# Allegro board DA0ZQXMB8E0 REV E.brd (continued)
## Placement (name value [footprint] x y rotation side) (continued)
PR202  *100k/f_4  [RC0402]  81.04 66.52 270 bottom
PR203  -  [RC0402]  84.75 66.3 270 bottom
PR204  *22.6k/f_4  [RC0402]  74.16 65.76 270 bottom
PR205  *100k/f_4  [RC0402]  82.8 62.56 180 bottom
PR206  -  [RC0402]  81.2 60.5 0 bottom
PR207  *2.2/f_6  [RC0603]  86.73 59.49 270 bottom
PR208  0.01/f_0612  [RC3216]  102.73 50.95 270 bottom
PR209  *short 0_4  [SHORT0402]  83.91 49.96 0 bottom
PR210  7.5_6  [RC0603]  81.2 49.79 0 bottom
PR211  *short 0_4  [SHORT0402]  83.91 48.8 0 bottom
PR212  10_6  [RC0603]  81.2 48.59 0 bottom
PR213  10k_4  [RC0402]  78.58 48.46 270 bottom
PR214  *100k_4  [RC0402]  76.55 47.7 180 bottom
PR215  -  [RC0402]  76.55 46.69 180 bottom
PR216  1/f_6  [RC0603]  57.9 46.46 180 bottom
PR217  *short 0_4  [SHORT0402]  50.69 46.15 180 bottom
PR218  -  [RC0402]  76.55 45.65 0 bottom
PR219  *short 0_4  [SHORT0402]  50.69 45.11 180 bottom
PR220  -  [RC0402]  72.89 45.11 270 bottom
PR221  *short 0_4  [SHORT0402]  73.91 45.11 270 bottom
PR222  *short 0_4  [SHORT0402]  76.55 44.63 0 bottom
PR223  -  [RC0402]  69.31 44.38 180 bottom
PR224  *short 0_6  [SHORT0603]  85.08 44.35 0 bottom
PR225  *short 0_4  [SHORT0402#2]  57.95 43.99 0 bottom
PR226  *short 0_4  [SHORT0402#2]  76.55 43.61 0 bottom
PR227  *0_4  [RC0402]  73.4 43.59 0 bottom
PR228  -  [RC0402]  57.95 42.95 0 bottom
PR229  -  [RC0402]  70.6 41.68 90 bottom
PR230  -  [RC0402]  78.48 40.54 270 bottom
PR231  *0_4  [RC0402]  79.49 40.54 90 bottom
PR232  10k_4  [RC0402]  80.51 40.54 90 bottom
PR233  -  [RC0402]  74.16 39.78 0 bottom
PR234  -  [RC0402]  106.16 39.65 180 bottom
PR235  10k_4  [RC0402]  108.45 39.65 180 bottom
PR236  22_8  [RC0805#2]  229.48 69.5 180 top
PR237  1m_6  [RC0603#2]  223.13 62 0 top
PR238  1m_6  [RC0603#2]  223.13 63.27 180 top
PR239  1m_6  [RC0603#2]  223.13 65.81 180 top
PR240  -  [RC0603#2]  223.13 64.54 180 top
PR241  -  [RC0402#2]  106.62 156.84 0 bottom
PR242  *short 0_4  [SHORT0402]  80.28 38.53 180 bottom
PU6  -  [QFN20-3X3-4-26P]  226.38 76.28 90 top
PU7  -  [QFN32-4X4-4-42P-1H]  78.5 64.19 180 top
PU8  tps54318rter  [QFN16-3X3-5-22P]  65.78 44.6 0 top
PU9  ev@nb671  [QFN14-3X3-4-16P#2]  100.8 156.19 270 bottom
PU10  nb670gq-z  [QFN14-3X3-4-16P]  211.14 151.87 0 bottom
PU11  -  [QFN20-3X3-4-21P-0_8H]  198.24 149.1 0 bottom
PU12  tps51211dscr  [SON10-3X3-5-16P]  196.51 137.62 0 bottom
PU13  as393mtr-e1  [SOIC8-6-1_27]  176.52 124.54 270 bottom
PU14  csd97374cq4m  [SON8-4_5X3_5-5-9P-SMT]  87.88 72.93 0 bottom
PU15  *csd97374cq4m  [SON8-4_5X3_5-5-9P-SMT]  88 63.7 0 bottom
PU16  nb671  [QFN14-3X3-4-16P]  54.12 45.95 90 bottom
PU17  bq24737rgrr  [PVQFN20-3_5X3_5-5-25P]  80.51 44.6 180 bottom
PU18  -  [SOT23-6-2_8-95-6P]  144.64 43.33 90 bottom
Q6  -  [SC70-2_1-65-6P]  91.05 144.43 90 top
Q7  ev@2n7002k  [SOT23_213-3_3-2#2]  155.95 144.05 90 top
Q8  -  [UMT_213-3-1_3]  96.13 141.63 0 top
Q9  ev@2n7002k  [SOT23_213-3_3-2]  160.01 141.63 90 top
Q10  -  [SC70-2_1-65-6P]  95.37 138.84 180 top
Q11  -  [SOT23_213-3_3-2#2]  155.95 137.44 0 top
Q12  ev@2n7002k  [SOT23_213-3_3-2]  154.04 130.46 90 top
Q13  -  [SOT23_213-3_3-2]  230.88 121.44 0 top
Q14  -  [SC70-2_1-65-6P]  145.15 119.66 180 top
Q15  -  [SOT23_213-3_3-2]  144.9 114.96 90 top
Q16  -  [SOT23_213-3_3-2]  111.24 114.58 270 top
Q17  -  [SC70-2_1-65-6P]  129.81 113.92 180 top
Q18  -  [SOT23_213-3_3-2]  215.92 111.63 90 top
Q19  -  [SOT23_213-3_3-2]  125.72 111.41 180 top
Q20  -  [SOT23_213-3_3-2]  147.95 104.8 90 top
Q21  -  [UMT_213-3-1_3]  26.53 47.65 270 top
Q22  -  [SOT23_213-3_3-2]  217.16 42.7 180 top
Q23  -  [SOT23_213-3_3-2]  17.39 42.57 0 top
Q24  -  [SOT23_213-3_3-2]  21.58 42.57 0 top
Q25  -  [SOT23_213-3_3-2]  33.39 42.57 0 top
Q26  -  [SC70-2_1-65-6P]  225.29 39.91 90 top
Q27  -  [SOT23_213-3_3-2]  17.39 38.76 180 top
Q28  -  [SOT23_213-3_3-2]  21.58 38.76 0 top
Q29  -  [SOT23_213-3_3-2#2]  140.58 160.68 0 bottom
Q30  -  [SC70-2_1-65-6P#2]  145.34 160.65 0 bottom
Q31  -  [UMT_213-3-1_3#2]  155.95 156.24 270 bottom
Q32  -  [SOT23_213-3_3-2#2]  160.52 155.73 270 bottom
Q33  -  [SOT23_213-3_3-2]  155.95 150.01 90 bottom
Q34  -  [SOT23_213-3_3-2#2]  159.38 139.09 0 bottom
Q35  -  [SOT23_213-3_3-2]  95.5 138.08 90 bottom
Q36  -  [SOT23_213-3_3-2#2]  156.07 135.03 90 bottom
Q37  -  [UMT_213-3-1_3#2]  156.84 129.82 90 bottom
Q38  -  [SOT23_213-3_3-2]  106.42 60.48 0 bottom
Q39  -  [UMT_213-3-1_3#2]  207.38 57.94 180 bottom
Q40  -  [UMT_213-3-1_3]  98.29 57.3 0 bottom
Q41  -  [SOT23_213-3_3-2]  150.74 55.65 90 bottom
Q42  -  [SOT23_213-3_3-2]  148.2 39.65 90 bottom
Q43  fdv301n  [SOT23_213-3_3-2]  153.28 39.65 270 bottom
Q44  -  [SC70-2_1-65-6P]  48.38 39.14 0 bottom
Q45  -  [SOT23_213-3_3-2]  20.57 36.6 270 bottom
Q53  -  [SOT23_213-3_3-2#2]  45.36 44.76 90 bottom
Q54  -  [SOT23_213-3_3-2#2]  219.96 131.5 90 top
R6  -  [SHORT0603]  80.26 153.32 0 top
R7  *100k_4  [RC0402]  92.96 153.06 0 top
R8  -  [RC0402#2]  105.02 153.06 0 top
R9  *0_4  [RC0402]  220.34 152.81 270 top
R10  *0_4  [RC0402]  221.35 152.81 270 top
R11  *0_4  [RC0402]  222.37 152.81 270 top
R12  -  [SHORT0603]  91.05 152.3 90 top
R13  -  [RC0402#2]  105.02 152.05 180 top
R14  *10k/f_4  [RC0402#2]  147.69 152.05 270 top
R15  ev@10k/f_4  [RC0402#2]  148.71 152.05 270 top
R16  *10k/f_4  [RC0402#2]  149.72 152.05 270 top
R17  sp@10k/f_4  [RC0402#2]  150.74 152.05 270 top
R18  *10k/f_4  [RC0402#2]  151.76 152.05 270 top
R19  *4.99k/f_4  [RC0402#2]  152.77 152.05 270 top
R20  -  [RC0402#2]  153.79 152.05 270 top
R21  sp@10k/f_4  [RC0402#2]  154.8 152.05 270 top
R22  -  [SHORT0603]  82.29 151.79 90 top
R23  -  [RC0402#2]  142.23 151.16 270 top
R24  -  [RC0402#2]  144.59 151.41 270 top
R25  -  [RC0402#2]  145.66 151.28 270 top
R26  -  [RC0402#2]  146.68 151.16 270 top
R27  -  [SHORT0603]  74.54 150.4 90 top
R28  -  [SHORT0603]  75.94 150.4 90 top
R29  ev@51.1/f_4  [RC0402#2]  131.69 150.27 90 top
R30  *short_8  [SHORT0805]  220.84 150.14 0 top
R31  -  [RC0402#2]  105.02 150.01 180 top
R32  -  [RC0402#2]  132.71 149.89 90 top
R33  sp@10k/f_4  [RC0402#2]  150.11 149.91 90 top
R34  -  [RC0402#2]  151.12 149.91 90 top
R35  -  [RC0402#2]  152.26 149.91 90 top
R36  sp@10k/f_4  [RC0402#2]  153.28 149.91 90 top
R37  sp@10k/f_4  [RC0402#2]  154.3 149.91 90 top
R38  -  [RC0402]  84.07 149.51 180 top
R39  -  [RC0402]  89.78 148.74 180 top
R40  -  [RC0402]  92.07 148.74 0 top
R41  ev@10k/f_4  [RC0402#2]  105.02 148.49 180 top
R42  *100k_4  [RC0402]  84.07 148.24 180 top
R43  ev@10k/f_4  [RC0402#2]  152.65 147.73 180 top
R44  -  [RC0402#2]  132.96 147.6 180 top
R45  ev@10k/f_4  [RC0402#2]  105.02 147.47 180 top
R46  *0_4  [RC0402]  89.78 147.22 0 top
R47  *0_4  [RC0402]  92.07 147.22 0 top
R48  10k_4  [RC0402]  95.24 147.22 90 top
R49  *100k_4  [RC0402]  93.84 146.97 90 top
R50  *0_4  [RC0402#2]  152.65 146.71 0 top
R51  ev@10k/f_4  [RC0402#2]  152.65 145.7 180 top
R52  -  [RC0402#2]  149.98 145.32 270 top
R53  *60.4_4  [RC0402#2]  120.13 144.81 90 top
R54  ev@10k/f_4  [RC0402#2]  159 144.81 270 top
R55  -  [RC0402#2]  118.87 144.81 90 top
R56  ev@10k/f_4  [RC0402]  105.02 144.43 0 top
R57  -  [RC0402#2]  160.77 144.3 180 top
R58  *60.4_4  [RC0402#2]  135.53 143.92 0 top
R59  *0_8  [RC0805]  221.99 143.03 0 top
R60  -  [SHORT0402#2]  222.75 141.12 0 top
R61  ev@10k/f_4  [RC0402]  156.2 141 0 top
R62  *10k/f_4  [RC0402#2]  154.68 140.49 270 top
R63  -  [SHORT0402#2]  222.75 140.11 0 top
R64  *0_4  [RC0402]  156.2 139.98 0 top
R65  10k_4  [RC0402]  92.7 139.6 270 top
R66  -  [SHORT0402]  222.75 139.09 0 top
R67  -  [RC0402]  98.29 138.84 270 top
R68  -  [SHORT0402#2]  99.56 138.84 270 top
R69  0_4  [RC0402]  100.58 138.84 270 top
R70  -  [SHORT0402]  220.72 138.46 270 top
R71  -  [SHORT0402]  222.75 138.08 0 top
R72  -  [SHORT0402]  222.75 137.06 0 top
R73  -  [RC0402#2]  105.02 135.54 180 top
R74  *0_4  [RC0402#2]  154.55 134.39 90 top
R75  *0_4  [RC0402#2]  155.82 134.39 90 top
R76  -  [RC0402#2]  105.02 133.5 0 top
R77  -  [SHORT0402]  95.14 132.92 270 top
R78  -  [RC0402]  96.41 132.92 270 top
R79  -  [RC0402#2]  105.02 132.23 180 top
R80  -  [RC0402#2]  138.29 131.98 270 top
R81  ev@10k/f_4  [RC0402#2]  150.99 131.98 180 top
R82  ev@10k/f_4  [RC0402]  105.02 131.09 0 top
R83  *0_4  [RC0402]  150.99 130.96 180 top
R84  -  [RC0402#2]  105.53 129.44 90 top
R85  ev@10k/f_4  [RC0402#2]  148.96 129.82 270 top
R86  ev@2.49k/f_4  [RC0402#2]  131.82 128.68 270 top
R87  10k_4  [RC0402]  198.75 126.27 0 top
R88  tpm@2.2_6  [RC0603]  225.8 124.23 180 top
R89  -  [RC0402]  231.77 123.98 0 top
R90  -  [RC0402]  228.21 122.46 270 top
R91  -  [RC0402]  143.76 121.44 180 top
R92  0_4  [RC0402]  146.04 121.44 0 top
R93  -  [RC0402]  225.42 120.68 180 top
R94  -  [RC0402]  153.61 120.12 180 top
R95  *20k_4  [RC0402]  227.7 119.92 0 top
R96  -  [RC0402]  227.7 120.93 180 top
R97  -  [RC0402]  143.76 117.88 180 top
R98  0_4  [RC0402]  146.04 117.88 0 top
R99  -  [RC0402]  211.5 117.3 180 top
R100  tpm@0_4  [RC0402]  214.06 116.44 180 top
R101  *short_8  [SHORT0805]  105.53 116.36 90 top
R102  10k_4  [RC0402]  107.31 115.85 270 top
R103  10k_4  [RC0402]  108.7 115.85 270 top
R104  4.7k_4  [RC0402]  130.93 115.6 180 top
R105  -  [RC0402]  217.24 114.48 180 top
R106  -  [RC0402]  221.61 114.2 180 top
R107  -  [RC0402]  190.01 114.1 90 top
R108  -  [RC0402]  191.05 114.1 90 top
R109  -  [RC0402]  193.16 114.1 90 top
R110  -  [RC0402]  194.17 114.1 90 top
R111  -  [RC0402]  195.22 114.1 90 top
R112  -  [RC0402]  196.28 114.1 90 top
R113  -  [RC0402]  197.32 114.1 90 top
R114  -  [RC0402]  198.37 114.1 90 top
R115  -  [RC0402]  199.51 114.1 90 top
R116  -  [RC0402]  192.14 114.07 90 top
R117  4.7k_4  [RC0402]  127.12 114.45 90 top
R118  -  [RC0402]  201.79 113.77 0 top
R119  1k_4  [RC0402]  108.7 113.57 90 top
R120  -  [RC0402]  188.33 113.57 180 top
R121  -  [RC0402]  165.98 113.06 180 top
R122  -  [RC0402]  201.79 112.73 0 top
R123  -  [RC0402]  131.06 112.17 0 top
R124  -  [RC0402]  128.92 112.14 180 top
R125  -  [SHORT0402#2]  121.94 112.42 180 top
R126  *0_4  [RC0402]  172.33 111.79 180 top
R127  -  [RC0402]  201.79 111.69 0 top
R128  -  [SHORT0402#2]  139.95 111.53 180 top
R129  -  [RC0603]  78.99 147.09 0 bottom
R133  *0_4  [RC0402]  172.33 110.77 180 top
R134  -  [RC0402]  135.75 110.64 180 top
R135  -  [RC0402]  201.79 110.64 0 top
R136  -  [RC0603]  143.63 110.52 270 top
R137  -  [RC0402]  139.95 110.26 180 top
R138  -  [SHORT0402#2]  132.86 110.06 90 top
R139  -  [SHORT0402#2]  134 110.06 90 top
R140  10k_4  [RC0402]  120.77 110.01 90 top
R141  10k_4  [RC0402]  121.91 110.01 90 top
R142  10k_4  [RC0402]  123.05 110.01 90 top
R143  10k_4  [RC0402]  128.9 110.01 90 top
R144  10k_4  [RC0402]  130.47 110.19 180 top
R145  -  [RC0402]  138.17 109.88 90 top
R146  -  [RC0402]  172.33 109.76 180 top
R147  10k_4  [RC0402]  135.75 109.63 180 top
R148  -  [RC0402]  201.79 109.58 0 top
R149  -  [RC0402]  172.33 108.74 180 top
R150  -  [RC0402]  201.79 108.54 0 top
R151  *100k_4  [RC0402]  144.26 108.23 0 top
R152  10k_4  [RC0402]  118.23 107.85 90 top
R153  10k_4  [RC0402]  119.5 107.85 90 top
R154  -  [RC0402]  120.77 107.85 90 top
R155  -  [RC0402]  121.91 107.85 90 top
R156  -  [RC0402]  124.2 107.85 90 top
R157  10k_4  [RC0402#3]  125.34 107.85 90 top
R158  10k_4  [RC0402]  126.61 107.85 270 top
R159  10k_4  [RC0402]  127.75 107.85 90 top
R160  8.2k_4  [RC0402]  128.9 107.85 90 top
R161  8.2k_4  [RC0402]  130.17 107.85 90 top
R162  10k_4  [RC0402]  131.31 107.85 90 top
R163  -  [RC0402]  132.45 107.85 90 top
R164  10k_4  [RC0402]  133.6 107.85 270 top
R165  10k_4  [RC0402]  134.74 107.85 90 top
R166  10k_4  [RC0402]  135.88 107.85 90 top
R167  sp@10k_4  [RC0402]  137.15 107.85 90 top
R168  10k_4  [RC0402]  138.17 107.85 270 top
R169  -  [RC0402]  139.31 107.85 270 top
R170  10k_4  [RC0402]  123.05 107.72 90 top
R171  -  [RC0603]  142.23 106.96 0 top
R172  -  [RC0402]  175.25 106.07 270 top
R173  -  [RC0402]  176.52 106.07 270 top
R174  -  [RC0402]  178.2 106.07 270 top
R175  -  [SHORT0603]  116.2 105.95 0 top
R176  10k_4  [RC0402]  118.23 105.69 270 top
R177  10k_4  [RC0402]  119.5 105.69 270 top
R178  10k_4  [RC0402]  120.77 105.69 90 top
R179  -  [RC0402]  121.91 105.69 90 top
R180  10k_4  [RC0402]  123.05 105.69 270 top
R181  10k_4  [RC0402]  124.2 105.69 90 top
R182  10k_4  [RC0402]  125.34 105.69 270 top
R183  -  [RC0402]  126.61 105.69 90 top
R184  10k_4  [RC0402]  127.75 105.69 270 top
R185  10k_4  [RC0402]  128.9 105.69 270 top
R186  -  [RC0402]  130.17 105.69 90 top
R187  10k_4  [RC0402]  131.31 105.69 270 top
R188  10k_4  [RC0402]  133.6 105.69 270 top
R189  10k_4  [RC0402]  134.74 105.69 270 top
R190  10k_4  [RC0402]  135.88 105.69 270 top
R191  sp@10k_4  [RC0402]  137.15 105.69 90 top
R192  -  [RC0402]  138.17 105.69 90 top
R193  1k_4  [RC0402]  139.31 105.69 90 top
R194  -  [SHORT0603]  142.23 105.56 0 top
R197  -  [RC0402]  175.25 103.79 90 top
R198  -  [RC0402]  176.52 103.79 90 top
R199  -  [RC0402]  178.2 103.79 90 top
R200  -  [RC0402]  118.74 103.66 0 top
R201  10k_4  [RC0402]  116.58 102.64 180 top
R202  -  [RC0402]  118.74 102.64 180 top
R203  -  [SHORT0402#2]  121.15 102.52 270 top
R204  -  [SHORT0603]  145.66 102.14 0 top
R205  10k_4  [RC0402]  116.58 101.5 180 top
R206  10k_4  [RC0402]  118.74 101.5 0 top
R207  10k_4  [RC0402]  140.96 101.37 180 top
R208  -  [RC0603]  103.88 101.25 180 top
R209  10k_4  [RC0402#2]  138.04 101.12 180 top
R210  -  [SHORT0402#2]  122.95 101.09 270 top
R211  10k_4  [RC0402]  140.96 100.36 180 top
R212  *short_8  [SHORT0805#2]  118.1 99.6 0 top
R213  -  [RC0402]  200.52 98.58 90 top
R214  *short_8  [SHORT0805]  114.61 98.49 0 top
R215  *short_8  [SHORT0805]  117.47 96.67 90 top
R216  -  [SHORT0603]  142.99 95.79 180 top
R217  -  [SHORT0402#2]  148.2 95.53 180 top
R218  10k_4  [RC0402]  135.68 95.05 0 top
R219  10k_4  [RC0402]  137.79 94.64 0 top
R220  -  [RC0402]  148.2 94.26 0 top
R221  -  [SHORT0603]  133.47 93.45 270 top
R222  -  [RC0402]  134.97 93.42 90 top
R223  -  [RC0402]  141.09 93.25 90 top
R224  -  [RC0402]  142.1 93.25 90 top
R225  -  [RC0402]  148.2 92.99 0 top
R226  -  [SHORT0603]  99.69 91.98 90 top
R227  -  [RC0402]  148.2 91.72 0 top
R228  -  [RC0402]  150.89 91.72 0 top
R229  -  [RC0402]  122.04 83.34 180 top
R230  *short_8  [SHORT0805]  124.96 82.96 180 top
R231  0_1206  [RC1206]  156.07 82.83 180 top
R232  -  [RC0402]  119.37 82.7 90 top
R233  -  [SHORT0402#2]  120.39 82.7 270 top
R234  -  [RC0402]  195.57 81.05 90 top
R235  *short_8  [SHORT0805#3]  124.83 80.93 180 top
R236  -  [RC0603]  129.15 80.29 270 top
R237  -  [RC0603]  130.55 80.29 270 top
R238  -  [RC0603]  132.25 80.29 90 top
R239  0_1206  [RC1206]  156.07 70 180 top
R240  -  [SHORT0603]  56.54 68.59 0 top
R241  -  [RC0805]  16.35 64.85 270 top
R242  -  [RC0402]  200.91 64.54 0 top
R245  -  [SHORT0402]  228.85 62.26 270 top
R246  -  [SHORT0402#2]  231.39 62.26 270 top
R247  -  [RC0402]  107.81 59.34 0 top
R248  -  [RC0402]  138.32 58.32 270 top
R249  -  [RC0402]  140.07 58.32 270 top
R250  -  [RC0402]  141.22 58.32 90 top
R251  -  [SHORT0402#2]  227.45 58.83 0 top
R252  -  [SHORT0402#2]  229.99 58.7 270 top
R253  -  [SHORT0402#2]  231 58.7 90 top
R254  -  [RC0402]  129.79 58.57 270 top
R255  1k_4  [RC0402]  130.93 58.57 90 top
R256  -  [RC0402]  219.96 57.94 90 top
R257  -  [RC0402]  220.97 57.94 90 top
R258  -  [SHORT0402#2]  117.72 57.69 0 top
R259  130/f_4  [RC0402]  120.01 57.69 180 top
R260  -  [RC0402]  122.29 57.56 180 top
R261  *51_4  [RC0402]  105.66 57.18 0 top
R262  *51_4  [RC0402]  114.8 56.8 0 top
R263  43_4  [RC0402]  122.29 56.54 0 top
R264  -  [RC0402]  128.26 56.16 180 top
R265  75_4  [RC0402]  119.24 55.91 90 top
R266  *75_4  [RC0402]  120.51 55.91 90 top
R267  -  [SHORT0603]  218.69 55.53 270 top
R268  -  [SHORT0402#2]  122.29 55.4 0 top
R269  51_4  [RC0402]  114.8 55.27 0 top
R270  -  [RC0402]  128.26 55.02 180 top
R271  51_4  [RC0402]  132.2 54.76 270 top
R272  51_4  [RC0402]  133.47 54.76 270 top
R273  51_4  [RC0402]  134.74 54.76 270 top
R274  -  [RC0402]  173.6 54.51 180 top
R275  -  [RC0402]  178.81 54.51 0 top
R276  *51_4  [RC0402]  114.8 54.13 180 top
R277  -  [SHORT0402#2]  116.96 54.13 180 top
R278  -  [SHORT0603]  159.25 53.24 0 top
R279  -  [SHORT0603]  173.6 53.27 0 top
R280  2/f_6  [RC0603]  177.41 52.99 180 top
R281  -  [RC0402]  180.08 52.99 270 top
R282  -  [SHORT0603]  173.52 51.54 0 top
R283  -  [RC0603]  177.41 51.59 180 top
R284  -  [RC0402]  157.6 51.46 90 top
R285  2/f_6  [RC0603]  160.01 51.21 90 top
R286  -  [RC0402]  161.28 51.08 270 top
R287  -  [RC0402]  219.19 51.39 180 top
R288  -  [RC0402]  180.59 50.7 90 top
R289  -  [RC0402]  173.45 50.29 180 top
R290  -  [RC0402]  178.81 50.19 0 top
R291  -  [RC0402]  29.33 49.94 0 top
R292  *0_4  [RC0402]  217.15 49.68 0 top
R293  1k_4  [RC0402]  29.33 48.92 180 top
R294  -  [SHORT0402#2]  217.15 48.67 180 top
R295  -  [RC0402]  161.28 48.41 270 top
R296  *short_8  [SHORT0805]  211.57 48.16 0 top
R297  -  [RC0402]  231.64 47.78 270 top
R299  47k_4  [RC0402]  216.88 46.84 270 top
R300  4.7k_4  [RC0402]  219.45 46.76 90 top
R301  1m_4  [RC0402]  24.88 45.11 0 top
R302  -  [RC0402]  31.49 45.11 0 top
R303  0_4  [RC0402]  109.08 44.22 0 top
R304  -  [RC0402]  223.13 44.22 0 top
R305  -  [SHORT0402#2]  13.45 43.84 90 top
R306  -  [RC0402]  14.72 43.84 90 top
R307  -  [RC0402]  24.88 43.84 180 top
R308  -  [RC0402]  122.42 43.84 0 top
R309  -  [RC0402]  231.13 43.72 270 top
R310  -  [SHORT0402#2]  220.62 43.62 270 top
R311  -  [RC0402]  219.6 43.59 270 top
R312  -  [RC0402]  109.08 42.95 180 top
R313  10k_4  [RC0402]  210.66 42.75 180 top
R314  -  [SHORT0402#2]  24.88 42.57 0 top
R315  *0_4  [RC0402]  221.86 41.81 0 top
R316  *100k_4  [RC0402]  210.66 41.73 0 top
R317  -  [SHORT0402#2]  24.88 41.3 0 top
R318  20k/f_4  [RC0402]  221.86 40.67 0 top
R319  -  [RC0402]  24.88 40.03 180 top
R320  *10k/f_4  [RC0402]  220.59 39.65 0 top
R321  -  [RC0402]  24.88 38.76 180 top
R322  -  [RC0402]  220.59 38.64 180 top
R323  -  [RC0402]  24.88 37.49 180 top
R324  -  [RC0402]  13.07 34.95 270 top
R325  -  [RC0402]  13.07 32.79 270 top
R326  -  [RC0402]  13.07 30.63 270 top
R327  -  [RC0402]  13.07 28.48 270 top
R328  -  [SHORT0402#3]  12.69 23.52 90 top
R329  -  [SHORT0402#2]  13.96 23.52 90 top
R330  -  [SHORT0402#2]  14.22 17.93 90 top
R331  -  [SHORT0402#2]  15.36 17.93 90 top
R332  -  [SHORT0402#2]  14.38 11.33 90 top
R333  -  [SHORT0402#2]  15.52 11.33 90 top
R334  -  [RC0402]  214.88 162.46 0 bottom
R335  *0_4  [RC0402]  217.16 162.46 180 bottom
R336  -  [SHORT0402#2]  220.72 162.46 180 bottom
R337  -  [RC0402#2]  134.61 161.95 0 bottom
R338  *0_4  [RC0402#2]  137.41 161.95 0 bottom
R339  ev@10k/f_4  [RC0402#2]  137.41 160.68 180 bottom
R340  -  [SHORT0402#2]  194.05 160.3 90 bottom
R341  -  [RC0402#2]  137.41 159.29 0 bottom
R342  *0_4  [RC0402#2]  132.71 159.03 90 bottom
R343  -  [RC0402#2]  144.26 158.9 180 bottom
R344  -  [RC0402#2]  146.42 158.9 0 bottom
R345  -  [RC0402]  139.69 158.14 0 bottom
R346  ev@100k/f_4  [RC0402#2]  136.77 157.63 90 bottom
R347  -  [RC0402#2]  157.98 156.87 270 bottom
R348  -  [RC0402#2]  132.71 156.75 270 bottom
R349  ev@100k/f_4  [RC0402#2]  153.92 156.75 90 bottom
R350  ev@10k/f_4  [RC0402#2]  146.04 156.49 270 bottom
R351  -  [RC0402#2]  147.06 156.49 270 bottom
R352  -  [RC0402#2]  148.07 156.49 270 bottom
R353  gms@4.99k/f_4  [RC0402#2]  137.91 156.36 90 bottom
R354  gms@4.99k/f_4  [RC0402#2]  139.18 156.36 90 bottom
R355  gms@4.99k/f_4  [RC0402#2]  140.45 156.36 90 bottom
R356  ev@10k/f_4  [RC0402#2]  146.04 154.46 270 bottom
R357  -  [RC0402#2]  147.06 154.46 270 bottom
R358  -  [RC0402#2]  153.92 154.46 90 bottom
R359  *4.99k/f_4  [RC0402#2]  137.91 154.33 270 bottom
R360  *4.99k/f_4  [RC0402#2]  139.18 154.33 270 bottom
R361  *4.99k/f_4  [RC0402#2]  140.45 154.33 90 bottom
R362  *10k/f_4  [RC0402#2]  155.19 153.19 270 bottom
R363  -  [RC0402#2]  156.46 153.19 90 bottom
R364  -  [RC0402#2]  161.28 153.06 180 bottom
R365  -  [RC0402#2]  105.02 147.98 180 bottom
R366  10k_4  [RC0402]  93.97 147.22 180 bottom
R367  -  [RC0402#2]  154.68 146.84 270 bottom
R368  -  [RC0402#2]  155.95 146.84 90 bottom
R369  *100k_4  [RC0402]  80.89 146.46 270 bottom
R370  -  [RC0402]  81.91 146.46 270 bottom
R371  -  [RC0402]  93.97 146.2 180 bottom
R372  -  [RC0402#2]  105.02 145.95 180 bottom
R373  *0_4  [RC0402#2]  93.97 145.19 0 bottom
R374  -  [RC0402#2]  105.02 144.93 0 bottom
R375  -  [SHORT0402#2]  93.97 144.17 0 bottom
R376  -  [RC0805]  155.19 143.92 270 bottom
R377  -  [SHORT0402#2]  88.21 143.59 270 bottom
R378  -  [SHORT0402#2]  89.22 143.59 270 bottom
R379  -  [SHORT0402#2]  91.13 143.59 270 bottom
R380  -  [SHORT0402#2]  92.14 143.59 270 bottom
R381  -  [RC0402]  155.57 138.71 0 bottom
R382  *0_4  [RC0402]  92.83 138.46 90 bottom
R383  -  [RC0402]  157.6 132.36 180 bottom
R384  -  [RC0402#2]  118.87 131.6 270 bottom
R385  ev@10k/f_4  [RC0402]  105.02 131.22 0 bottom
R386  *100k/f_4  [RC0402]  154.8 130.58 90 bottom
R387  -  [RC0402#2]  105.02 130.08 180 bottom
R388  4.7k_4  [RC0402]  206.62 129.44 270 bottom
R389  4.7k_4  [RC0402]  207.64 129.44 270 bottom
R390  4.7k_4  [RC0402]  209.92 129.44 270 bottom
R391  4.7k_4  [RC0402]  210.94 129.44 270 bottom
R392  43_4  [RC0402]  211.95 129.44 90 bottom
R393  -  [RC0402]  214.37 129.44 270 bottom
R394  10k_4  [RC0402]  199.51 129.21 270 bottom
R395  -  [RC0402]  201.79 129.19 180 bottom
R396  -  [RC0402]  203.83 129.19 0 bottom
R397  *0_4  [RC0402#2]  158.87 129.06 90 bottom
R398  -  [RC0402#2]  159.88 129.06 90 bottom
R399  ev@100k/f_4  [RC0402#2]  160.9 129.06 90 bottom
R400  0_4  [RC0402#2]  191.76 130.58 0 bottom
R401  -  [RC0402]  154.8 128.3 90 bottom
R402  -  [RC0402#2]  105.02 127.79 0 bottom
R403  0_4  [RC0402#2]  199.18 127.69 0 bottom
R404  0_4  [RC0402]  186.48 125.68 0 bottom
R405  0_4  [RC0402]  190.11 126.49 90 bottom
R406  -  [SHORT0402#2]  191.13 126.39 90 bottom
R407  0_4  [RC0402]  192.17 128.65 270 bottom
R408  4.7k_4  [RC0402]  198.62 126.14 0 bottom
R409  ev@10k/f_4  [RC0402#2]  142.23 125.5 0 bottom
R410  -  [RC0402#2]  133.09 125 90 bottom
R411  4.7k_4  [RC0402]  198.62 125 0 bottom
R412  10k_4  [RC0402]  220.59 124.36 180 bottom
R413  -  [RC0603]  197.1 123.73 180 bottom
R414  -  [RC0603]  220.59 123.09 180 bottom
R415  -  [SHORT0402]  155.69 121.06 270 bottom
R416  10k_4  [RC0402]  156.71 121.06 90 bottom
R417  -  [RC0402]  198.62 120.93 0 bottom
R418  -  [RC0402]  144.14 120.55 270 bottom
R419  -  [RC0402]  156.2 119.53 0 bottom
R420  *22_4  [RC0402]  220.08 119.41 270 bottom
R421  -  [SHORT0603]  142.1 118.65 0 bottom
R422  15_4  [RC0402]  144.14 118.26 270 bottom
R423  15_4  [RC0402]  155.69 118.01 270 bottom
R424  -  [RC0402]  220.59 117.88 180 bottom
R425  15_4  [RC0402]  145.41 115.09 90 bottom
R426  15_4  [RC0402]  146.42 115.09 90 bottom
R427  15_4  [RC0402]  147.44 115.09 90 bottom
R428  15_4  [RC0402]  148.45 115.09 90 bottom
R429  15_4  [RC0402]  150.61 115.09 270 bottom
R430  15_4  [RC0402]  151.76 115.09 270 bottom
R431  -  [RC0402]  187.98 114.1 90 bottom
R432  -  [RC0402]  188.99 114.1 90 bottom
R433  -  [RC0402]  190.01 114.1 90 bottom
R434  -  [RC0402]  191.05 114.1 90 bottom
R435  -  [RC0402]  193.16 114.1 90 bottom
R436  -  [RC0402]  194.17 114.1 90 bottom
R437  -  [RC0402]  195.22 114.1 90 bottom
R438  -  [RC0402]  196.28 114.1 90 bottom
R439  -  [RC0402]  197.32 114.1 90 bottom
R440  -  [RC0402]  198.37 114.1 90 bottom
R441  -  [RC0402]  199.51 114.1 90 bottom
R442  -  [RC0402]  132.58 114.07 0 bottom
R443  -  [RC0402]  192.14 114.07 90 bottom
R444  -  [RC0402]  132.58 113.06 0 bottom
R445  *0_4  [RC0402]  143.25 111.66 180 bottom
R446  10k_4  [RC0402]  159.12 110.9 90 bottom
R447  10k_4  [RC0402#2]  128.9 110.01 270 bottom
R448  -  [RC0402]  130.17 110.01 270 bottom
R449  10k_4  [RC0402]  131.18 110.01 270 bottom
R450  -  [SHORT0402#2]  132.33 110.01 90 bottom
R451  10k_4  [RC0402]  133.34 110.01 90 bottom
R452  10k_4  [RC0402]  135.25 110.01 270 bottom
R453  -  [RC0402]  144.14 110.01 270 bottom
R454  10k_4  [RC0402]  117.21 109.63 0 bottom
R455  10k_4  [RC0402]  126.84 109.53 180 bottom
R456  10k_4  [RC0402]  159.12 108.87 90 bottom
R457  -  [RC0402]  201.79 108.54 0 bottom
R458  10k_4  [RC0402]  117.09 107.85 90 bottom
R459  10k_4  [RC0402]  118.23 107.85 90 bottom
R460  10k_4  [RC0402]  119.5 107.85 90 bottom
R461  -  [RC0402]  120.77 107.85 90 bottom
R462  -  [SHORT0402#2]  121.91 107.85 90 bottom
R463  -  [RC0402]  124.2 107.85 90 bottom
R464  -  [RC0402]  125.34 107.85 270 bottom
R465  -  [RC0402]  128.9 107.85 270 bottom
R466  -  [RC0402]  130.17 107.85 90 bottom
R467  *0_4  [RC0402]  135.25 107.85 270 bottom
R468  *0_4  [RC0402]  136.26 107.85 90 bottom
R469  sp@10k_4  [RC0402]  137.28 107.85 90 bottom
R470  10k_4  [RC0402]  138.29 107.85 270 bottom
R471  *8.2k_4  [RC0402]  141.09 107.85 270 bottom
R472  sp@10k_4  [RC0402]  142.23 107.85 90 bottom
R473  10k_4  [RC0402]  143.37 107.85 270 bottom
R474  10k_4  [RC0402]  127.75 107.82 270 bottom
R475  *100k_4  [RC0402]  131.33 107.77 270 bottom
R476  10k_4  [RC0402]  123.05 107.72 90 bottom
R477  10k_4  [RC0402]  126.61 107.72 90 bottom
R478  -  [RC0402]  149.19 107.52 180 bottom
R479  *0_4  [RC0402]  151.32 107.52 180 bottom
R480  -  [RC0402]  201.79 107.49 0 bottom
R481  1m_4  [RC0402]  149.19 106.3 0 bottom
R482  -  [SHORT0402#2]  151.32 106.3 0 bottom
R483  -  [RC0402]  114.29 105.95 0 bottom
R484  -  [SHORT0402#3]  143.37 105.82 90 bottom
R485  10k_4  [RC0402]  144.39 105.82 90 bottom
R486  10k_4  [RC0402]  117.09 105.69 270 bottom
R487  10k_4  [RC0402]  118.23 105.69 270 bottom
R488  10k_4  [RC0402]  119.5 105.69 270 bottom
R489  10k_4  [RC0402]  120.77 105.69 90 bottom
R490  10k_4  [RC0402]  121.91 105.69 90 bottom
R491  10k_4  [RC0402]  123.05 105.69 270 bottom
R492  10k_4  [RC0402]  124.2 105.69 90 bottom
R493  -  [RC0402]  125.34 105.69 270 bottom
R494  -  [RC0402]  126.61 105.69 90 bottom
R495  10k_4  [RC0402]  127.75 105.69 270 bottom
R496  10k_4  [RC0402]  128.9 105.69 90 bottom
R497  -  [RC0402]  130.17 105.69 90 bottom
R498  10k_4  [RC0402]  131.31 105.69 90 bottom
R499  10k_4  [RC0402]  132.45 105.69 90 bottom
R500  -  [RC0402]  135.12 105.69 90 bottom
R501  10k_4  [RC0402]  136.26 105.69 90 bottom
R502  sp@10k_4  [RC0402]  137.28 105.69 90 bottom
R503  -  [RC0402]  138.55 105.69 90 bottom
R504  10k_4  [RC0402]  139.56 105.69 90 bottom
R505  8.2k_4  [RC0402]  141.09 105.69 90 bottom
R506  sp@10k_4  [RC0402]  142.23 105.69 90 bottom
R507  -  [RC0402]  201.79 105.59 0 bottom
R508  10m_4  [RC0402]  146.3 105.31 180 bottom
R509  1k_4  [RC0402]  209.03 105.31 270 bottom
R510  10k_4  [RC0402]  149.19 105.13 180 bottom
R511  -  [SHORT0402#2]  151.32 105.13 0 bottom
R512  -  [RC0402]  114.29 104.55 0 bottom
R513  -  [RC0402]  151.32 103.89 180 bottom
R514  *330k_4  [RC0402]  149.22 103.86 0 bottom
R515  10k_4  [RC0402]  114.29 103.41 0 bottom
R516  -  [SHORT0603]  211.07 103.28 180 bottom
R517  20k/f_4  [RC0402]  213.48 102.64 180 bottom
R518  -  [SHORT0402#2]  149.27 102.62 0 bottom
R519  -  [RC0402]  151.43 102.62 0 bottom
R520  -  [RC0402]  114.29 102.26 180 bottom
R521  -  [SHORT0603]  104.51 101.63 270 bottom
R522  -  [RC0603]  106.16 101.63 270 bottom
R523  *short_8  [SHORT0805]  107.94 101.63 90 bottom
R524  20k/f_4  [RC0402]  213.48 101.63 180 bottom
R525  *330k_4  [RC0402]  147.44 101.37 180 bottom
R526  -  [RC0402]  149.6 101.37 0 bottom
R527  -  [RC0402]  114.29 101.12 0 bottom
R528  -  [RC0402]  201.16 100.36 0 bottom
R529  -  [RC0402]  147.44 100.23 0 bottom
R530  -  [RC0402]  151.76 100.23 0 bottom
R531  10k_4  [RC0402]  114.29 99.6 0 bottom
R532  -  [RC0402]  149.6 99.09 0 bottom
R533  -  [RC0402]  112.26 98.45 0 bottom
R534  -  [RC0402]  114.29 98.45 180 bottom
R535  0_4  [RC0402]  147.44 97.82 180 bottom
R536  -  [RC0402]  149.6 97.82 0 bottom
R537  -  [RC0402]  114.29 96.55 180 bottom
R538  -  [RC0402]  113.66 94.9 90 bottom
R539  0_4  [RC0402]  114.8 94.9 270 bottom
R540  -  [SHORT0603]  103.75 93.63 90 bottom
R541  8.2k_4  [RC0402]  114.42 93.37 180 bottom
R542  -  [RC0402]  172.84 88.55 0 bottom
R543  -  [RC0402]  200.91 87.66 0 bottom
R544  -  [RC0402]  172.84 87.4 0 bottom
R545  1m_4  [RC0402]  110.99 85.75 0 bottom
R546  -  [RC0402]  114.29 84.86 180 bottom
R547  *0_4  [RC0402]  114.29 78.77 180 bottom
R548  *0_4  [RC0402]  114.29 77.75 180 bottom
R549  10k_4  [RC0402]  114.29 76.48 180 bottom
R550  10k_4  [RC0402]  114.29 75.47 180 bottom
R551  *0_4  [RC0402]  112.01 72.04 270 bottom
R552  *0_4  [RC0402]  113.28 72.04 270 bottom
R553  -  [RC0402]  200.91 68.86 0 bottom
R554  -  [SHORT0402#2]  230.12 62.26 270 bottom
R555  *0_8  [RC0805]  111.75 61.5 270 bottom
R556  -  [RC0402]  109.97 60.99 270 bottom
R557  *100k/f_4  [RC0402]  97.53 59.34 180 bottom
R558  -  [RC0402]  103.88 59.08 90 bottom
R559  -  [RC0402]  101.46 57.94 180 bottom
R560  -  [RC0402]  128.64 57.94 90 bottom
R561  -  [RC0402]  130.29 57.94 90 bottom
R562  -  [RC0402]  132.96 57.69 180 bottom
R563  4.7k_4  [RC0402#2]  210.63 57.18 0 bottom
R564  -  [RC0402]  113.91 57.05 270 bottom
R565  10k_4  [RC0402]  115.05 57.05 90 bottom
R566  -  [RC0402]  116.7 57.05 270 bottom
R567  -  [RC0402]  117.85 57.05 90 bottom
R568  51_4  [RC0402]  118.99 57.05 270 bottom
R569  56_4  [RC0402]  123.05 57.05 270 bottom
R570  150_6  [RC0603]  120.26 56.92 270 bottom
R571  0_4  [RC0402]  132.96 56.54 0 bottom
R572  -  [SHORT0402#2]  141.98 56.54 270 bottom
R573  -  [RC0402]  148.2 56.54 270 bottom
R574  4.7k_4  [RC0402#2]  210.63 56.03 180 bottom
R575  150k/f_4  [RC0402#2]  206.11 55.91 0 bottom
R576  68.1k/f_4  [RC0402#3]  208.14 55.91 0 bottom
R577  -  [RC0402]  128.64 55.65 270 bottom
R578  62_4  [RC0402]  123.05 55.02 90 bottom
R579  -  [RC0402]  124.2 55.02 270 bottom
R580  10k_4  [RC0402]  113.91 54.89 90 bottom
R581  0_4  [RC0402]  117.85 54.89 90 bottom
R582  -  [SHORT0402#2]  116.37 54.87 270 bottom
R583  -  [RC0402]  35.93 53.62 90 bottom
R584  -  [SHORT0603]  39.49 53.24 180 bottom
R585  *short_8  [SHORT0805]  28.44 52.99 90 bottom
R586  -  [RC0402]  194 52.15 270 bottom
R587  10k_4  [RC0402]  147.69 50.57 270 bottom
R588  -  [SHORT0402#2]  150.74 50.07 180 bottom
R589  -  [SHORT0603]  206.37 50.07 90 bottom
R590  -  [SHORT0603]  204.59 50.07 90 bottom
R591  -  [SHORT0603]  208.53 50.07 90 bottom
R592  -  [SHORT0603]  210.43 50.07 90 bottom
R593  *0_4  [RC0402]  29.33 49.94 0 bottom
R594  -  [RC0402]  154.3 50.4 0 bottom
R595  *0_4  [RC0402]  155.95 49.18 270 bottom
R596  -  [RC0402]  156.96 49.18 270 bottom
R597  -  [RC0402]  29.33 48.92 0 bottom
R598  *0_4  [RC0402]  154.3 48.67 0 bottom
R599  0_4  [RC0402]  221.73 48.29 0 bottom
R600  *0_4  [RC0402]  220.21 48.03 90 bottom
R601  *0_4  [RC0402]  152.14 47.53 0 bottom
R602  -  [SHORT0402#2]  156.46 47.53 0 bottom
R603  *0_4  [RC0402]  221.73 47.27 0 bottom
R604  -  [SHORT0402#2]  147.82 46.38 0 bottom
R605  *0_4  [RC0402]  152.14 46.38 0 bottom
R606  *0_4  [RC0402]  154.3 46.38 0 bottom
R607  *0_4  [RC0402]  156.46 46.38 0 bottom
R608  *0_4  [RC0402]  152.9 45.24 0 bottom
R609  *0_4  [RC0402]  115.18 45.11 270 bottom
R610  10k_4  [RC0402]  39.49 45.16 0 bottom
R611  10k_4  [RC0402]  41.52 45.16 180 bottom
R612  *0_4  [RC0402]  147.57 44.73 90 bottom
R613  *0_4  [RC0402]  148.71 44.73 90 bottom
R614  -  [SHORT0402#2]  149.85 44.73 270 bottom
R615  10k_4  [RC0402]  150.99 44.73 270 bottom
R616  10k_4  [RC0402]  152.9 44.1 180 bottom
R617  -  [SHORT0402#2]  39.49 44.15 180 bottom
R618  -  [SHORT0402#2]  41.52 44.15 0 bottom
R619  -  [RC0402]  115.18 43.08 90 bottom
R620  -  [RC0402]  148.07 43.08 0 bottom
R621  -  [RC0402]  34.41 42.95 270 bottom
R622  *0/j_4  [RC0402]  36.06 42.95 90 bottom
R623  10k_4  [RC0402]  154.3 42.32 180 bottom
R625  -  [RC0402]  49.27 42.19 180 bottom
R626  *0_4  [RC0402]  49.27 41.05 180 bottom
R627  1k_4  [RC0402]  150.74 40.54 90 bottom
R628  1k_4  [RC0402]  150.74 38.25 270 bottom
R629  4.7k_4  [RC0402]  224.4 38.13 90 bottom
R630  56_4  [RC0402]  225.42 38.13 270 bottom
R631  56_4  [RC0402]  226.43 38.13 270 bottom
R632  4.7k_4  [RC0402]  227.45 38.13 90 bottom
R633  *100k/f_4  [RC0402]  23.11 37.49 90 bottom
R634  *0_4  [RC0402]  47.49 37.11 0 bottom
R635  -  [RC0402]  49.78 36.91 180 bottom
R636  -  [RC0402]  13.58 35.46 180 bottom
R637  -  [RC0402]  13.58 34.44 180 bottom
R638  -  [RC0402]  13.58 33.3 180 bottom
R639  -  [RC0402]  13.58 32.29 180 bottom
R640  -  [RC0402]  13.58 31.14 180 bottom
R641  -  [RC0402]  13.58 30.13 180 bottom
R642  -  [RC0402]  13.58 28.98 180 bottom
R643  -  [RC0402]  13.58 27.97 180 bottom
R644  ev@10k/f_4  [RC0402#2]  155.82 152.05 270 top
R645  -  [RC0402#2]  154.3 53.37 270 bottom
R646  *0_4  [RC0402#2]  224.86 114.48 270 top
R647  tpmn@0_4  [RC0402#2]  225.87 114.48 90 top
R648  -  [RC0402#2]  225.42 119.41 0 top
R649  tpmn@0_4  [RC0402#2]  225.42 118.39 0 top
R650  tpmn@0_4  [RC0402]  221.35 114.84 270 bottom
R651  *2m/f_4  [RC0402#2]  153.28 53.37 90 bottom
R652  75/f_6  [RC0603#2]  51.93 67.08 270 top
R653  75/f_6  [RC0603#3]  50.66 67.08 270 top
R654  75/f_6  [RC0603#2]  44.31 67.08 270 top
R655  75/f_6  [RC0603#2]  43.04 67.08 270 top
R758  tpmn@0_4  [RC0402#2]  204.95 121.92 0 top
R775  -  [RC0402#2]  45.58 44.22 180 top
R776  -  [RC0603#2]  47.74 44.1 270 top
R780  *0_4  [RC0402#2]  220.72 135.03 0 top
R781  -  [RC0805#2]  215.08 132.44 270 top
R782  *100k_4  [RC0402#2]  219.19 134.52 90 top
RP6  -  [10P8R]  139.82 115.22 180 top
RP7  *10k_10p8r  [10P8R]  192.04 46.48 270 bottom
RV6  -  [CC0402]  13.83 42.06 180 top
SW6  -  [SW-TC901-AA1G-A160T-6P]  208.22 159.2 0 bottom
SW7  -  [SW-TME-532-V-6P]  229.86 68.35 270 bottom
TP6  *  [TP2650]  223.38 153.32 0 top
TP7  *  [TP2050]  140.15 152.12 0 top
TP8  *  [TP2675#2]  143.25 150.14 0 top
TP9  *  [TP2050]  144.01 147.73 0 top
TP10  *  [TP2675#2]  143.25 143.92 0 top
TP11  *  [TP2650#2]  128.26 142.09 0 top
TP13  -  [TP2675]  205.68 114.91 0 top
TP14  -  [TP2675]  205.78 112.98 0 top
TP15  *  [TP2650]  210.56 111.03 0 top
TP16  -  [TP2675#2]  140.33 106.83 0 top
TP17  -  [TP2675]  132.45 105.82 0 top
TP18  -  [TP2675]  139.06 104.19 270 top
TP19  -  [TP2675]  135.78 104.17 270 top
TP20  -  [TP2675]  133.27 103.96 270 top
TP21  -  [TP2675]  131.11 103.71 0 top
TP22  *  [TP2650]  128.74 104.12 270 top
TP23  -  [TP2675]  145.63 103.43 0 top
TP24  pad  [TP2650]  140.22 103.02 270 top
TP25  -  [TP2675]  137.35 102.72 0 top
TP26  -  [TP2675]  129.43 102.67 0 top
TP27  -  [TP2675]  135.37 102.26 270 top
TP29  -  [TP2675]  131.44 101.37 270 top
TP30  -  [TP2675]  135.65 100.31 0 top
TP31  -  [TP2675]  133.75 100.2 270 top
TP32  -  [TP2675]  141.72 99.34 0 top
TP33  -  [TP2675]  137.91 99.9 270 top
TP34  -  [TP2675]  139.82 99.09 0 top
TP35  -  [TP2675]  122.5 98.2 270 top
TP36  -  [TP2675]  120.51 97.82 270 top
TP37  -  [TP2675]  141.55 97.18 0 top
TP38  -  [TP2675]  136.9 96.55 270 top
TP39  -  [TP2675]  139.21 96.55 0 top
TP40  -  [TP2675]  115.31 95.02 270 top
TP41  -  [TP2675]  115.31 93.12 270 top
TP42  *  [TP2650]  116.96 92.99 270 top
TP43  *  [TP2650]  118.23 92.99 270 top
TP44  pad  [TP2650]  133.34 83.21 90 top
TP45  -  [TP2675]  134.99 82.2 270 top
TP46  -  [TP2675]  136.92 82.02 270 top
TP47  pad  [TP2650]  133.34 81.94 90 top
TP48  pad  [TP2650]  133.34 80.67 90 top
TP49  *  [TP2650]  122.67 59.34 90 top
TP50  pad  [TP2650]  123.94 59.34 270 top
TP51  pad  [TP2650]  125.21 59.34 270 top
TP52  pad  [TP2650]  126.48 59.34 270 top
TP53  pad  [TP2650]  136.9 59.34 270 top
TP54  pad  [TP2650]  115.05 59.29 270 top
TP55  *  [TP2650]  116.32 59.29 90 top
TP56  *  [TP2650]  117.59 59.29 270 top
TP57  pad  [TP2650]  118.86 59.29 270 top
TP58  *  [TP2650]  120.13 59.29 270 top
TP59  pad  [TP2650]  134.61 59.21 270 top
TP60  pad  [TP2650]  127.75 58.96 270 top
TP61  pad  [TP2650]  123.94 58.07 270 top
TP62  pad  [TP2650]  125.21 58.07 270 top
TP63  pad  [TP2650]  126.48 58.07 270 top
TP64  pad  [TP2650]  136.9 58.07 270 top
TP65  pad  [TP2650]  134.61 57.94 90 top
TP66  pad  [TP2650]  127.75 57.56 270 top
TP67  pad  [TP2650]  126.69 56.8 270 top
TP68  pad  [TP2650]  136.9 56.8 270 top
TP69  pad  [TP2650]  134.61 56.67 270 top
TP70  pad  [TP2650]  125.39 56.8 270 top
TP71  *  [TP2650]  32.63 54 180 top
TP72  *  [TP2650]  221.96 54.03 0 top
TP73  *  [TP2650]  31.79 52.96 180 top
TP74  *  [TP2650]  218.94 162.46 180 bottom
TP75  *  [TP2650]  212.21 162.31 180 bottom
TP76  *  [TP2650]  204.84 155.35 180 bottom
TP77  *  [TP2650]  203.42 153.32 180 bottom
TP78  *  [TP2650#2]  125.72 147.03 180 bottom
TP79  *  [TP2650#2]  126.36 141.63 180 bottom
TP80  *  [TP2650]  215.66 130.02 180 bottom
TP81  *  [TP2650]  205.53 129.06 180 bottom
TP82  *  [TP2650]  197.63 127.26 180 bottom
TP83  -  [TP2675]  196.03 127 180 bottom
TP84  *  [TP2650]  200.14 126.27 180 bottom
TP85  *  [TP2050]  144.64 125 180 bottom
TP86  *  [TP2050]  146.04 125 180 bottom
TP87  *  [TP2050]  147.57 125 180 bottom
TP88  *  [TP2050]  148.84 125 180 bottom
TP90  *  [TP2650]  223.54 119.74 180 bottom
TP92  *  [TP2650]  127.63 111.03 270 bottom
TP93  -  [TP2675]  120.06 109.27 180 bottom
TP94  -  [TP2675]  132.55 107.98 270 bottom
TP95  -  [TP2675]  139.82 107.6 270 bottom
TP96  *  [TP2650]  134.1 107.55 270 bottom
TP97  *  [TP2650]  133.87 106.09 270 bottom
TP98  *  [TP2650]  133.85 104.8 270 bottom
TP99  pad  [TP2650]  111.62 104.42 270 bottom
TP100  pad  [TP2650]  144.26 104.4 270 bottom
TP101  pad  [TP2650]  110.18 103.94 270 bottom
TP102  -  [TP2675]  206.39 99.77 180 bottom
TP103  -  [TP2675]  111.7 99.39 180 bottom
TP104  *  [TP2650]  111.62 79.4 270 bottom
TP105  *  [TP2650]  112.89 79.96 270 bottom
TP106  *  [TP2650]  114.55 72.54 270 bottom
TP107  *  [TP2650]  226.43 71.91 180 bottom
TP108  *  [TP2650]  114.55 71.27 270 bottom
TP109  *  [TP2650]  232.35 63.15 180 bottom
TP110  pad  [TP2650]  114.93 58.7 270 bottom
TP111  pad  [TP2650]  146.04 58.45 270 bottom
TP112  pad  [TP2650]  147.41 58.32 270 bottom
TP113  *  [TP2650]  121.66 57.43 90 bottom
TP114  *  [TP2650]  121.66 56.16 270 bottom
TP115  pad  [TP2650]  115.05 55.27 270 bottom
TP116  *  [TP2650]  112.79 55.09 270 bottom
TP117  *  [TP2650]  121.07 54.99 270 bottom
TP118  *  [TP2650]  31.11 53.24 0 bottom
TP119  -  [TP2675#2]  119.22 49.58 180 bottom
TP120  -  [TP2675#2]  116.2 45.24 180 bottom
TP121  *  [TP2650#2]  223.08 114.58 0 top
TP122  *  [TP2650#2]  223.36 112.88 0 top
U6  -  [SOT23-2_8-95-6P]  99.56 134.9 180 top
U7  -  [SSOP5-P-A-TOSHIBA-B]  197.86 124.23 180 top
U8  tpms@npct620/650_tssop28  [TSSOP28-6_4-65-SLB9635TT]  220.08 120.07 90 top
U9  tc7sh08fu  [SSOP5-P-A-TOSHIBA-B]  153.41 118.14 0 top
U10  -  [SOIC8-6-1_27]  177.54 110.01 90 top
U12  -  [BGA96-ELPIDA-EDJ4216EBBG-DJ-F]  190.87 106.33 90 top
U13  -  [BGA96-ELPIDA-EDJ4216EBBG-DJ-F]  190.87 93.12 90 top
U14  -  [BGA96-ELPIDA-EDJ4216EBBG-DJ-F]  190.87 73.18 90 top
U15  -  [BGA96-ELPIDA-EDJ4216EBBG-DJ-F]  190.87 59.97 90 top
U16  *74cbtlv3126  [VQFN14-3_5X3_5-5-15P]  109.34 56.16 270 top
U17  -  [QFN48-6X6-4-49P-ALC280]  225.24 49.06 270 top
U18  -  [SOT23-5]  217.16 39.4 180 top
U19  ev@sn74ahc1g32dckr  [SSOP5-P-A-TOSHIBA-B]  134.74 158.27 90 bottom
U20  -  [BGA595-NVIDIA-N13P-GV2-S-A2]  140.41 139.7 180 bottom
U21  bma250e  [SENSOR-2X2-5-12P-1H]  190.36 128.68 180 bottom
U22  -  [SSOP5-P-A-TOSHIBA-B#2]  160.9 125.88 90 bottom
U23  -  [SSOP5-P-A-TOSHIBA-B#2]  157.32 125.07 180 bottom
U24  -  [SOIC8-8-1_27]  149.98 119.15 90 bottom
U25  it8380e-192/cx  [LQFP128-16X16-4-1_6H]  209.67 118.77 270 bottom
U26  -  [BGA96-ELPIDA-EDJ4216EBBG-DJ-F]  190.87 106.33 270 bottom
U27  -  [BGA96-ELPIDA-EDJ4216EBBG-DJ-F]  190.87 93.12 270 bottom
U28  -  [BGA1168-INTEL-HASWELL]  130.42 81.2 90 bottom
U29  -  [BGA96-ELPIDA-EDJ4216EBBG-DJ-F]  190.87 73.18 270 bottom
U30  -  [TRF-9_4-1_27-24P]  47.49 63.27 180 bottom
U31  -  [SOT353-1-2_125-65-5P]  114.29 61.5 90 bottom
U32  -  [BGA96-ELPIDA-EDJ4216EBBG-DJ-F]  190.87 59.97 270 bottom
U33  74aup1g07gw  [SOT353-1-2_125-65-5P]  145.03 56.54 180 bottom
U34  *cm1293a-04so  [TSOP6-2_8-95]  44.19 55.53 90 bottom
U35  *cm1293a-04so  [TSOP6-2_8-95]  50.03 55.53 90 bottom
U36  rtl8111gs-cg  [QFN32-4X4-4-33P-0_9H]  34.15 49.43 270 bottom
U37  74aup1g07gw  [SOT353-1-2_125-65-5P]  148.84 48.29 180 bottom
U38  tc7sh08fu  [SSOP5-P-A-TOSHIBA-B]  155.82 44.35 180 bottom
U39  74aup1g07gw  [SOT353-1-2_125-65-5P]  156.46 39.65 270 bottom
U40  -  [MSOP8-4_9-65]  14.22 23.9 0 bottom
VRAM6  -  [BGA96-HYNIX-H5TQ1G63AFP]  112.22 147.7 270 top
VRAM7  -  [BGA96-HYNIX-H5TQ1G63AFP]  112.22 128.7 90 top
VRAM8  -  [BGA96-HYNIX-H5TQ1G63AFP]  112.22 147.7 270 bottom
VRAM9  -  [BGA96-HYNIX-H5TQ1G63AFP]  112.22 128.7 90 bottom
Y6  ev@27mhz  [XTL-3_2X2_5-2_2X1_6]  142.99 156.11 180 bottom
Y7  32.768khz  [XTAL-8_4X3_7-5_5X2_8]  148.96 110.77 0 bottom
Y8  24mhz  [XTL-3_2X2_5-2_2X1_7-0_8H]  109.97 82.58 0 bottom
Y9  -  [XTL-3_2X2_5-2_2X1_7]  35.17 56.8 180 bottom

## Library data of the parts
BT6 = ML1220-SMT
C6 C77 C80 C81 C166 C179 C180 C184 C196-C198 C202 C235-C238 C242 C243 C245 C247 C248 C250 C252-C257 C259 C260 C262 C264-C269 C271 C274 C282 C285 C446 C454 C455 C460 C461 C523 PC13 PC14 PC16 PC39 PC40 PC45 PC48 PC51 PC57 PC64 PC66 PC70 PC75 PC77-PC81 PC97 PC98 PC101 PC102 PC104 PC117 PC120-PC122 PC124 PC125 PC133 PC139 PC141 PC142 PC162 PC163 PC179 PC185 PC187 = CC0805
C7 C8 C10-C19 C21-C34 C41 C50-C53 C55-C57 C64 C67 C68 C70 C71 C78 C79 C82 C84-C87 C92 C102 C104-C106 C108 C110 C112-C122 C124-C129 C131 C135 C136 C138-C146 C148 C152-C154 C156 C160-C165 C167 C169-C178 C182 C183 C186 C188-C193 C195 C199-C201 C203-C213 C221-C232 C234 C239 C241 C246 C249 C251 C258 C261 C263 C270 C272 C273 C275 C279 C281 C284 C286 C287 C290-C297 C299-C318 C320-C331 C333 C334 C336 C338-C353 C356 C357 C359 C361-C378 C380-C394 C397-C409 C411-C422 C424-C439 C441-C445 C447-C453 C456 C457 C462 C463 C465-C469 C472-C478 C480-C491 C493 C495 C497 C499-C506 C508 C509 C512 C513 C515-C517 C519 C520 C522 C524 C525 C527 C529-C540 C542 C545-C550 C552-C561 C563-C581 C583-C586 C588 C589 C692-C695 C713-C717 D20 D22-D28 PC7 PC9 PC12 PC15 PC17-PC20 PC22 PC24 PC27 PC30 PC32-PC34 PC36 PC41 PC43 PC44 PC46 PC47 PC49 PC50 PC52 PC54 PC58 PC60-PC63 PC71-PC74 PC84 PC89 PC92 PC94 PC95 PC100 PC103 PC107 PC110 PC111 PC114-PC116 PC123 PC129 PC135 PC140 PC144 PC149-PC158 PC161 PC164 PC171 PC173 PC176 PC178 PC180 PC181 PC183 PC186 PC189 PC195 RV6 = CC0402
C9 C20 C35-C40 C42-C49 C54 C58-C63 C65 C66 C69 C72-C76 C83 C88-C91 C94-C101 C103 C107 C109 C111 C123 C130 C132-C134 C137 C147 C157 C158 C168 C181 C185 C187 C194 C214-C220 C233 C240 C244 C276-C278 C280 C288 C289 C298 C319 C332 C335 C337 C354 C355 C358 C360 C379 C396 C410 C423 C440 C458 C459 C464 C479 C492 C494 C496 C498 C507 C510 C511 C514 C518 C526 C528 C541 C543 C544 C551 C587 C712 PC6 PC8 PC10 PC11 PC21 PC23 PC25 PC26 PC28 PC29 PC31 PC35 PC37 PC38 PC42 PC53 PC55 PC56 PC59 PC65 PC67-PC69 PC76 PC82 PC83 PC85-PC88 PC91 PC93 PC96 PC99 PC105 PC109 PC112 PC113 PC118 PC126 PC128 PC130 PC132 PC134 PC136 PC137 PC145 PC147 PC148 PC159 PC160 PC165 PC169 PC172 PC174 PC175 PC177 PC182 PC184 PC188 PC190-PC194 = CC0603
C93 D6 D7 L21-L23 PR10 PR11 PR19 PR30 PR31 PR45 PR51 PR53 PR63 PR64 PR73 PR96 PR105 PR110 PR118-PR123 PR154 PR160 PR163 PR170 PR171 PR197 PR207 PR210 PR212 PR216 PR237-PR240 R88 R129 R136 R171 R208 R236-R238 R280 R283 R285 R413 R414 R522 R570 R652-R655 R776 = RC0603
C283 = CC1808
C395 C521 C562 = CC3528
C470 C471 PC90 PC119 PC146 = CC7343
C582 PC168 PC170 = CC1206
CN6 = BSH-030-01-L-D-A-TR-60P-LDH
CN7 = GS12401-1011-40P-R-NH-SMT
CN8 = MINICARD-110021-52131-52P-RUV
CN9 = 50224-01001-001-10P-L
CN10 = 50271-0040N-V01-4P-L
CN11 = 50501-0300N-001-30P-L
CN12 = RJ45-JM361C-HP34AA03-9H-8P
CN13 = 51553-01041-001-10P-L
CN14 = 50565-02601-001-26P-L
CN15 = 88266-040XX-XXX-4P-L
CN16 = 50501-00801-001-8P-L
CN17 = 50505-0080N-V01-8P-L
CN18 = HDMI-59075-01942-001-19P
CN19 = USB-YBA-USB-032-P01-9P-RUH-SMT
CP6-CP11 = 8P4R
D8-D13 D15-D19 D21 PD6 PD7 PD13 = DSM
D14 = DSMV
D29 PQ7-PQ18 PQ20-PQ23 PQ27-PQ29 PQ31 PQ33 PQ35 PQ38 PQ43-PQ46 PQ52 PQ64 PQ65 PQ67 Q7 Q9 Q11-Q13 Q15 Q16 Q18-Q20 Q22-Q25 Q27-Q29 Q32-Q36 Q38 Q41-Q43 Q45 Q53 Q54 = SOT23_213-3_3-2
HOLE6 HOLE8 = H-C236D140P2
HOLE7 = HG-C276D118P2
HOLE9 HOLE11 HOLE13 = H-C146D146N
HOLE10 = HG-C315D146P2
HOLE12 HOLE15-HOLE17 = HG-C315D118P2
HOLE14 = HG-C315D158P2
J6 J7 = JOPEN25X30_S
JDIM6 = DDR-C-2013289-204P
JP6-JP18 = SHORT3720
L6-L8 L15-L17 PR6 PR8 PR9 PR12 PR13 PR15-PR18 PR20-PR23 PR25 PR26 PR29 PR32 PR35 PR37-PR43 PR46-PR49 PR54 PR55 PR57-PR59 PR62 PR65 PR68 PR69 PR71 PR72 PR74 PR76-PR81 PR83-PR95 PR97-PR99 PR101 PR104 PR106 PR111-PR115 PR126-PR131 PR134 PR135 PR137-PR141 PR143 PR144 PR148 PR151-PR153 PR156 PR159 PR161 PR169 PR172-PR175 PR177-PR180 PR183 PR188 PR189 PR191 PR192 PR194 PR195 PR198-PR206 PR213-PR215 PR218 PR220 PR223 PR227-PR235 PR241 R7-R11 R13-R21 R23-R26 R29 R31-R58 R61 R62 R64 R65 R67 R69 R73-R76 R78-R87 R89-R100 R102-R113 R115-R124 R126 R127 R133-R135 R137 R140-R170 R172-R174 R176-R193 R197-R202 R205-R207 R209 R211 R213 R218-R220 R222-R225 R227-R229 R232 R234 R242 R247-R250 R254-R257 R259-R266 R269-R276 R281 R284 R286-R293 R295 R297 R299-R304 R306-R309 R311-R313 R315 R316 R318-R327 R334 R335 R337-R339 R341-R374 R381-R405 R407-R412 R416-R420 R422-R449 R451-R461 R463-R481 R483 R485-R510 R512-R515 R517 R519 R520 R524-R539 R541-R553 R556-R569 R571 R573-R581 R583 R586 R587 R593-R601 R603 R605-R613 R615 R616 R619-R623 R625-R651 R758 R775 R780 R782 = RC0402
L9-L12 L18 L19 PR33 PR44 PR50 PR56 PR116 PR117 PR147 PR181 PR184 PR236 R59 R241 R376 R555 R781 = RC0805
L20 = L3_2X2_5-3_2
MR6 = SOT23_123-2_8-1_9
PC106 PC108 PC127 PC131 PC138 PC143 PC166 PC167 = ECAP6_3X6_1-7_2
PD8-PD10 PQ6 PQ19 PQ30 PQ66 Q8 Q21 Q31 Q37 Q39 Q40 = UMT_213-3-1_3
PD11 = D-DO-214AC
PD12 = POWER-6_5-1_84-3P
PJ6 = 20288-04XX-4P-L
PJ7 = 50458-00801-V02-8P-L
PL6 PL9 = CHOKE-ETQP4LR36AFM
PL7 PL8 PL10 PL11 PL14-PL16 = CHOKE-PCMC063T-3R3MN-SMT
PL12 PL13 = CHOKE-PCMC063T-R82MN-4P-SMT
PQ24 = IMD
PQ25 PQ26 PQ40-PQ42 PQ48-PQ51 = WDFN5-3_05X3_05-65
PQ32 PQ34 PQ36 PQ37 PQ39 PQ47 = SO-8FL-5P-OA
PQ53 Q6 Q10 Q14 Q17 Q26 Q30 Q44 = SC70-2_1-65-6P
PR7 PR24 PR28 PR34 PR36 PR61 PR66 PR67 PR70 PR75 PR82 PR100 PR102 PR103 PR107-PR109 PR133 PR142 PR145 PR149 PR150 PR155 PR157 PR158 PR162 PR164-PR168 PR182 PR186 PR187 PR196 PR209 PR211 PR217 PR219 PR221 PR222 PR225 PR226 PR242 R60 R63 R66 R68 R70-R72 R77 R125 R128 R138 R139 R203 R210 R217 R233 R245 R246 R251-R253 R258 R268 R277 R294 R305 R310 R314 R317 R328-R333 R336 R340 R375 R377-R380 R406 R415 R450 R462 R482 R484 R511 R518 R554 R572 R582 R588 R602 R604 R614 R617 R618 = SHORT0402
PR14 PR27 PR52 PR124 PR125 PR132 PR146 PR176 PR190 PR224 R6 R12 R22 R27 R28 R175 R194 R204 R216 R221 R226 R240 R267 R278 R279 R282 R421 R516 R521 R540 R584 R589-R592 = SHORT0603
PR60 PR193 R30 R101 R212 R214 R215 R230 R235 R296 R523 R585 = SHORT0805
PR136 R231 R239 = RC1206
PR185 PR208 = RC3216
PU6 = QFN20-3X3-4-26P
PU7 = QFN32-4X4-4-42P-1H
PU8 = QFN16-3X3-5-22P
PU9 PU10 PU16 = QFN14-3X3-4-16P
PU11 = QFN20-3X3-4-21P-0_8H
PU12 = SON10-3X3-5-16P
PU13 U10 = SOIC8-6-1_27
PU14 PU15 = SON8-4_5X3_5-5-9P-SMT
PU17 = PVQFN20-3_5X3_5-5-25P
PU18 = SOT23-6-2_8-95-6P
R114 = RC0402: signal model: RC0402_36/F_4
RP6 RP7 = 10P8R
SW6 = SW-TC901-AA1G-A160T-6P
SW7 = SW-TME-532-V-6P
TP6 TP11 TP15 TP22 TP24 TP42-TP44 TP47-TP82 TP84 TP90 TP92 TP96-TP101 TP104-TP118 TP121 TP122 = TP2650
TP7 TP9 TP85-TP88 = TP2050
TP8 TP10 TP13 TP14 TP16-TP21 TP23 TP25-TP27 TP29-TP41 TP45 TP46 TP83 TP93-TP95 TP102 TP103 TP119 TP120 = TP2675
U6 = SOT23-2_8-95-6P
U7 U9 U19 U22 U23 U38 = SSOP5-P-A-TOSHIBA-B
U8 = TSSOP28-6_4-65-SLB9635TT
U12-U15 U26 U27 U29 U32 = BGA96-ELPIDA-EDJ4216EBBG-DJ-F
U16 = VQFN14-3_5X3_5-5-15P
U17 = QFN48-6X6-4-49P-ALC280
U18 = SOT23-5
U20 = BGA595-NVIDIA-N13P-GV2-S-A2
U21 = SENSOR-2X2-5-12P-1H
U24 = SOIC8-8-1_27
U25 = LQFP128-16X16-4-1_6H
U28 = BGA1168-INTEL-HASWELL
U30 = TRF-9_4-1_27-24P
U31 U33 U37 U39 = SOT353-1-2_125-65-5P
U34 U35 = TSOP6-2_8-95
U36 = QFN32-4X4-4-33P-0_9H
U40 = MSOP8-4_9-65
VRAM6-VRAM9 = BGA96-HYNIX-H5TQ1G63AFP
Y6 = XTL-3_2X2_5-2_2X1_6
Y7 = XTAL-8_4X3_7-5_5X2_8
Y8 = XTL-3_2X2_5-2_2X1_7-0_8H
Y9 = XTL-3_2X2_5-2_2X1_7

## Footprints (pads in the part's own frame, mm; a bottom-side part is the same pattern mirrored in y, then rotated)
8P4R
  rect 0.406x1.092 smd: 1(-1.194,-0.8) 2(-1.194,0.8) 3(-0.406,-0.8) 4(-0.406,0.8) 5(0.406,-0.8) 6(0.406,0.8) 7(1.194,-0.8) 8(1.194,0.8)
10P8R
  rect 0.305x1.092 smd: 1(-1.27,-0.85) 2(-0.635,-0.85) 3(0,-0.85) 4(0.635,-0.85) 5(1.27,-0.85) 6(1.27,0.85) 7(0.635,0.85) 8(0,0.85) 9(-0.635,0.85) 10(-1.27,0.85)
20288-04XX-4P-L
  round 1.295 hole 0.889: 3(1.25,0)
50271-0040N-V01-4P-L
  rect 2.108x2.997 smd: 5(-4.425,0)
50501-0300N-001-30P-L
  rect 0.305x1.295 smd: 1(-7.25,2.8) 2(-6.75,2.8) 3(-6.25,2.8) 4(-5.75,2.8) 5(-5.25,2.8) 6(-4.75,2.8) 7(-4.25,2.8) 8(-3.75,2.8) 9(-3.25,2.8) 10(-2.75,2.8) 11(-2.25,2.8) 12(-1.75,2.8) 13(-1.25,2.8) 14(-0.75,2.8) 15(-0.25,2.8) 16(0.25,2.8) 17(0.75,2.8) 18(1.25,2.8) 19(1.75,2.8) 20(2.25,2.8) 21(2.75,2.8) 22(3.25,2.8) 23(3.75,2.8) 24(4.25,2.8) 25(4.75,2.8) 26(5.25,2.8) 27(5.75,2.8) 28(6.25,2.8) 29(6.75,2.8) 30(7.25,2.8)
  rect 1.803x1.397 smd: 31(-8.9,0) 32(8.9,0)
50505-0080N-V01-8P-L
  rect 0.61x1.295 smd: 1(-3.5,3.25) 2(-2.5,3.25) 3(-1.5,3.25) 4(-0.5,3.25) 7(2.5,3.25) 8(3.5,3.25)
  rect 0.991x2.007 smd: 9(-6.1,0) 10(6.1,0)
50565-02601-001-26P-L
  rect 0.508x1.092 smd: 1(-10,1.65) 2(-9.2,1.65) 3(-8.4,1.65) 4(-7.6,1.65) 5(-6.8,1.65) 6(-6,1.65) 7(-5.2,1.65) 8(-4.4,1.65) 9(-3.6,1.65) 10(-2.8,1.65) 11(-2,1.65) 12(-1.2,1.65) 13(-0.4,1.65) 14(0.4,1.65) 15(1.2,1.65) 16(2,1.65) 17(2.8,1.65) 18(3.6,1.65) 19(4.4,1.65) 20(5.2,1.65) 21(6,1.65) 22(6.8,1.65) 23(7.6,1.65) 24(8.4,1.65) 25(9.2,1.65) 26(10,1.65)
  rect 2.388x2.21 smd: 27(-12.4,0) 28(12.4,0)
51553-01041-001-10P-L
  rect 0.305x0.838 smd: 1(-2.25,3.175) 2(-1.75,3.175) 3(-1.25,3.175) 4(-0.75,3.175) 5(-0.25,3.175) 6(0.25,3.175) 7(0.75,3.175) 10(2.25,3.175)
88266-040XX-XXX-4P-L
  rect 0.787x2.007 smd: 1(-1.875,4.05) 2(-0.625,4.05) 3(0.625,4.05) 4(1.875,4.05)
  rect 2.007x2.489 smd: 5(-4.075,0)
BGA96-ELPIDA-EDJ4216EBBG-DJ-F
  round 0.356 smd: A1(-3.2,6) A2(-2.4,6) A3(-1.6,6) A7(1.6,6) A8(2.4,6) A9(3.2,6) B1(-3.2,5.2) B2(-2.4,5.2) J8(2.4,-0.4) J9(3.2,-0.4) K1(-3.2,-1.2) K2(-2.4,-1.2) K3(-1.6,-1.2) K7(1.6,-1.2) K8(2.4,-1.2) L1(-3.2,-2) L2(-2.4,-2) L3(-1.6,-2) L7(1.6,-2) L8(2.4,-2) L9(3.2,-2) M1(-3.2,-2.8) M2(-2.4,-2.8) M3(-1.6,-2.8) M7(1.6,-2.8) M8(2.4,-2.8) R2(-2.4,-5.2) R3(-1.6,-5.2) R9(3.2,-5.2) T1(-3.2,-6) T2(-2.4,-6) T3(-1.6,-6) T7(1.6,-6) T8(2.4,-6) T9(3.2,-6)
